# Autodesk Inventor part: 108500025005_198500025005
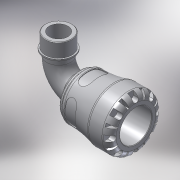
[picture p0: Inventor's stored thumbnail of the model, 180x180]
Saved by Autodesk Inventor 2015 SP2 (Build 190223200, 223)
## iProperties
Created: 2016-12
Part Number: 108500025005_198500025005
Material: PVC-Piping
Description: PLASSON 90° ELBOW WITH THREADED MALE OFFTAKE 25X1/2" SERIES 1
Document SubType Name: Modeling
Designer: KIM
Mass: 87.5276 g
Surface Area: 208.81 cm^2
Volume: 62.5197 cm^3
Density: 1.4 g/cm^3
Appearance: Smooth - White
Author: KIM
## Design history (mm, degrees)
derived "1085.ipt"
feature "Solid1::1085.ipt"
tag "TaggingFeature1"
body "Solid1"
other parameters: "d1" = 20.16, "d2" = 25, "d3" = 31.25, "d4" = 47, "d8" = 39.95, "d13" = 6.3, "d14" = 6.3, "d15" = 0, "d17" = 360 deg, "d19" = 8 deg, "d20" = 0.5, "d21" = 0.5, "d22" = 8 deg, "d24" = 0, "d26" = 360 deg, "d33" = 4.7, "d43" = 36.66, "d51" = 0.47, "d54" = 8.75, "d55" = 5.5, "d57" = 12.348, "d58" = 0, "d74" = 0, "d78" = 48, "d82" = 0.5, "d115" = 360 deg, "d207" = 90 deg, "d228" = 7.4375, "d247" = 0.94, "d248" = 2.88, "d268" = 21.9725, "d269" = 2.88, "d270" = 74, "d276" = 20.955, "d277" = 16, "d278" = 23.0505, "d279" = 44, "d280" = 17.6, "d281" = 3.14325, "d283" = 18.8595, "d286" = 0, "d287" = 0, "d288" = 14.6685, "d290" = 8.90025, "d292" = 30 deg, "d_" = 25, "E_" = 47, "l_" = 48, "A_" = 74, "A_1" = 44, "l_2" = 16, "R_" = 20.955, "d9" = 7.875, "d11" = 47, "d12" = 31.25, "d289" = 14.6685
